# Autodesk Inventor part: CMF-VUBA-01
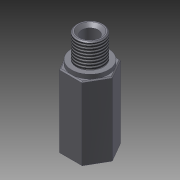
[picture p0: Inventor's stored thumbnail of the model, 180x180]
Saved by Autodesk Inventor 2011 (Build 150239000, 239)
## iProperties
Created: 2016-10
Part Number: CMF-VUBA-01
Material: Сталь
Document SubType Name: Modeling
Designer: Хитров
Density: 7.85 g/cm^3
Author: Хитров
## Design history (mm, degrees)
sketch "Эскиз1"
  geometry: L1 (10.97, 0)-(5.485, -9.5); L2 (5.485, -9.5)-(-5.485, -9.5); L3 (-5.485, -9.5)-(-10.97, 0); L4 (-10.97, 0)-(-5.485, 9.5); L5 (-5.485, 9.5)-(5.485, 9.5); L6 (5.485, 9.5)-(10.97, 0); 2 further points
  constraints: 12 end point, 1 coincident, 13 other
  dimensions: "d0" = 19 distance between parallel lines of L2 L5
extrude "Выдавливание1" new body sketch "Эскиз1" distance "d1" = 36; taper "d2" = 0 deg
sketch "Эскиз2"
  geometry: C1 r 9 at (0, 0); 1 further point
  constraints: 1 centre point, 1 coincident
  dimensions: "d3" = 18 diameter of C1
extrude "Выдавливание2" join sketch "Эскиз2" distance "d4" = 2; taper "d5" = 0 deg
sketch "Эскиз3"
  geometry: C1 r 9 at (0, 0) reference; C2 r 6.58 at (0, 0)
  constraints: 1 centre point, 1 coincident
  dimensions: "d6" = 13.16 diameter of C2
extrude "Выдавливание3" join sketch "Эскиз3" distance "d7" = 12; taper "d8" = 0 deg
chamfer "Фаска1" distance "d9" = 0.5; stored, may be unused: second distance "d10" = 2, angle "d11" = 45 deg
feature "Резьба1" dims "d12" = 8, "d13" = 0
hole "Отверстие1" diameter "d16" = 11.445; stored, may be unused: countersink angle "d20" = 90 deg, drill point angle "d22" = 118 deg; dims "d14" = 10, "d15" = 10, "d17" = 10, "d18" = 4, "d19" = 2, "d21" = 35
hole "Отверстие2" diameter "d25" = 8; stored, may be unused: countersink angle "d29" = 90 deg, drill point angle "d31" = 118 deg; dims "d23" = 10, "d24" = 10, "d26" = 10, "d27" = 4, "d28" = 2, "d30" = 35
chamfer "Фаска2" distance "d32" = 1.5; stored, may be unused: second distance "d33" = 2, angle "d34" = 45 deg
chamfer "Фаска3" distance "d35" = 0.5; stored, may be unused: second distance "d36" = 2, angle "d37" = 45 deg
node "Твердое тело1"
